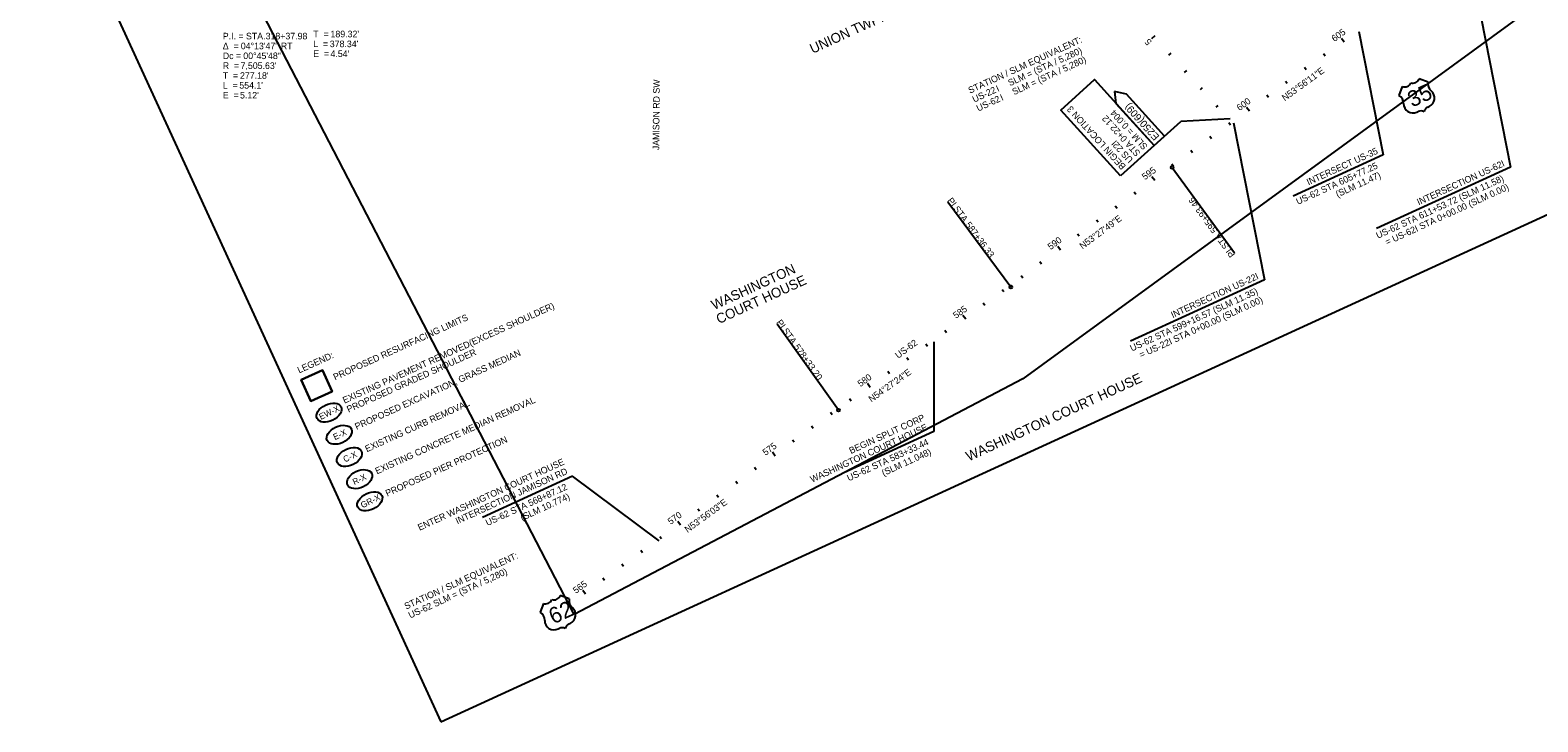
# Model space of a CAD drawing. Extents: x 127199 to 143299, y 479188 to 491521.
# Drawn here: x 127199 to 133628, y 479188 to 482138 of the extents above; entities that cross this region are included whole.
import ezdxf

# ---------------------------------------------------------------- set-up
doc = ezdxf.new("R2010")
doc.units = 0
for name, color, linetype in [('PM_P_CL_Double_Solid', 7, 'Continuous'), ('PM_X_CL_Double_Solid', 7, 'Continuous'), ('PM_X_CL_Pass_Proh_Lt', 7, 'Continuous'), ('PM_X_Crosswalk', 7, 'Continuous'), ('PM_X_Lane_Line', 7, 'Continuous'), ('PM_X_Stop_Line', 7, 'Continuous'), ('PV_X_Parking_Lot', 7, 'Continuous'), ('PV_X_Walk', 7, 'Continuous'), ('RD_X_RR_2', 7, 'Continuous'), ('SH_Data', 7, 'Continuous')]:
    doc.layers.add(name, color=color, linetype=linetype)

msp = doc.modelspace()

# ---------------------------------------------------------------- linework, layer by layer
at = {"layer": 'PM_P_CL_Double_Solid'}
msp.add_lwpolyline([(128487.4, 480597.5), (128396.5, 480555.8), (128354.8, 480646.7), (128445.7, 480688.4)], close=True, dxfattribs=at)
at = {"layer": 'PM_X_CL_Double_Solid'}
for p, q in [((132069.3, 481552.7), (132334.2, 481188.9)), ((131380.6, 481042.4), (131112.7, 481404)), ((130645.7, 480517.4), (130384.1, 480883.6))]:
    msp.add_line(p, q, dxfattribs=at)
for centre in [(132069.3, 481552.7), (131380.6, 481042.4), (130645.7, 480517.4)]:
    msp.add_circle(centre, 6, dxfattribs=at)
at = {"layer": 'PM_X_CL_Pass_Proh_Lt'}
for centre, major_axis in [((128474, 480506.8), (51.4, 24.9)), ((128517.4, 480412.2), (51.7, 24.5)), ((128560.8, 480317.5), (51.4, 24.9)), ((128604.2, 480222.9), (-51.4, -24.9)), ((128647.6, 480128.3), (51.4, 24.9))]:
    msp.add_ellipse(centre, major_axis=major_axis, ratio=0.62608, dxfattribs=at)
at = {"layer": 'PM_X_Crosswalk'}
for p, q in [((133049.6, 481897.4), (133035.7, 481859.7)), ((133159.7, 481916.6), (133122, 481930.6)), ((133158.6, 481809.8), (133163.8, 481812.1)), ((133112.1, 481788.4), (133117.3, 481790.8)), ((129387.7, 479693.2), (129373.7, 479655.5)), ((129497.7, 479712.3), (129460, 479726.3)), ((129450.1, 479584.2), (129455.3, 479586.6)), ((129496.6, 479605.5), (129501.8, 479607.9))]:
    msp.add_line(p, q, dxfattribs=at)
for centre, radius, start, end in [((133059.3, 481924.1), 28.4, 250.2093, 339.06331), ((133095.4, 481940.7), 28.4, 250.2093, 339.06331), ((133198.8, 481909.4), 39.8, 169.63538, 230.08918), ((133147.6, 481848.5), 39.8, 293.99804, 49.80439), ((133015.5, 481825.4), 39.8, 359.18343, 59.63724), ((133095.1, 481824.4), 39.8, 179.46823, 295.27457), ((133170.5, 481783.9), 28.4, 114.63631, 167.76641), ((133129.1, 481765), 28.4, 61.5062, 114.63631), ((129397.3, 479719.9), 28.4, 250.2093, 339.06331), ((129433.5, 479736.5), 28.4, 250.2093, 339.06331), ((129536.8, 479705.2), 39.8, 169.63538, 230.08918), ((129353.6, 479621.1), 39.8, 359.18343, 59.63724), ((129433.1, 479620.2), 39.8, 179.46823, 295.27457), ((129485.6, 479644.3), 39.8, 293.99804, 49.80439), ((129467.2, 479560.8), 28.4, 61.5062, 114.63631), ((129508.5, 479579.7), 28.4, 114.63631, 167.76641)]:
    msp.add_arc(centre, radius, start, end, dxfattribs=at)
at = {"layer": 'PM_X_Lane_Line'}
for p, q in [((133330.5, 482471.2), (133511.4, 481554.3)), ((132864.5, 482131.8), (132968.2, 481606.2)), ((131873.3, 481865.4), (131822.7, 481877)), ((131822.7, 481877), (131829.1, 481825.5)), ((131829.1, 481825.5), (131991.5, 481645.7)), ((132035.7, 481685.6), (131873.3, 481865.4)), ((131991.5, 481645.7), (132105.9, 481749)), ((132315.6, 481759.3), (132105.9, 481749)), ((132330.5, 481742.9), (132462.5, 481073.3)), ((131991.5, 481645.7), (132035.7, 481685.6)), ((132968.2, 481606.2), (132584.1, 481430.1)), ((133511.4, 481554.3), (132939.9, 481292.2)), ((132462.5, 481073.3), (131891.1, 480811.2)), ((131052.8, 480808.2), (131052.2, 480426.5)), ((131052.2, 480426.5), (130668.1, 480250.4)), ((129511.8, 480236.1), (129127.7, 480059.9)), ((129881, 479960.4), (129511.8, 480236.1))]:
    msp.add_line(p, q, dxfattribs=at)
msp.add_lwpolyline([(131848, 481516), (131593.9, 481797.2), (131737.4, 481926.9), (131991.5, 481645.7)], close=True, dxfattribs=at)
at = {"layer": 'PV_X_Walk'}
for p, q in [((131995.3, 482113.9), (131980.4, 482100.5)), ((132802.1, 482086.4), (132790.3, 482102.5)), ((132062.3, 482039.7), (132053.4, 482031.7)), ((132721.2, 482027.5), (132714.2, 482037.2)), ((132129.3, 481965.5), (132120.4, 481957.5)), ((132640.4, 481968.6), (132633.3, 481978.3)), ((132196.4, 481891.3), (132187.5, 481883.3)), ((132559.6, 481909.8), (132552.5, 481919.5)), ((132263.4, 481817.1), (132254.5, 481809.1)), ((132397.9, 481792), (132386.1, 481808.2)), ((132478.7, 481850.9), (132471.7, 481860.6)), ((132317.1, 481733.2), (132310, 481742.9)), ((132236.2, 481674.3), (132229.2, 481684)), ((132155.4, 481615.4), (132148.3, 481625.1)), ((132074.5, 481556.6), (132067.5, 481566.3)), ((131994.2, 481497.1), (131982.3, 481513.1)), ((131913.8, 481437.5), (131906.7, 481447.2)), ((131833.5, 481378), (131826.3, 481387.6)), ((131753.1, 481318.5), (131746, 481328.1)), ((131672.8, 481258.9), (131665.6, 481268.6)), ((131592.4, 481199.4), (131580.5, 481215.5)), ((131512.1, 481139.9), (131504.9, 481149.5)), ((131351, 481021.3), (131344, 481031.1)), ((131431.7, 481080.3), (131424.6, 481090)), ((131269.6, 480963.2), (131262.7, 480972.9)), ((131188.3, 480905), (131176.7, 480921.3)), ((131106.9, 480846.9), (131099.9, 480856.7)), ((131025.5, 480788.8), (131018.6, 480798.5)), ((130944.2, 480730.6), (130937.2, 480740.4)), ((130862.8, 480672.5), (130855.8, 480682.3)), ((130781.4, 480614.4), (130769.8, 480630.7)), ((130700.1, 480556.3), (130693.1, 480566)), ((130618.9, 480497.9), (130611.8, 480507.6)), ((130457.2, 480380.1), (130450.1, 480389.8)), ((130538, 480439), (130531, 480448.7)), ((130376.4, 480321.3), (130364.6, 480337.4)), ((130295.5, 480262.4), (130288.5, 480272.1)), ((130214.7, 480203.5), (130207.6, 480213.2)), ((130133.9, 480144.6), (130126.8, 480154.3)), ((130053, 480085.8), (130046, 480095.5)), ((129972.2, 480026.9), (129960.4, 480043.1)), ((129891.4, 479968), (129884.3, 479977.7)), ((129810.5, 479909.2), (129803.5, 479918.9)), ((129729.7, 479850.3), (129722.6, 479860)), ((129568, 479732.5), (129556.3, 479748.7)), ((129648.9, 479791.4), (129641.8, 479801.1))]:
    msp.add_line(p, q, dxfattribs=at)
at = {"layer": 'RD_X_RR_2'}
for p, q in [((137214.6, 484869.1), (131432.3, 480651.5)), ((129519.3, 479645.5), (127687.9, 483180.9)), ((127199.5, 483005.6), (128950.3, 479187.9)), ((128950.3, 479187.9), (134131.4, 481564)), ((131432.3, 480651.5), (129519.3, 479645.5))]:
    msp.add_line(p, q, dxfattribs=at)
at = {"layer": 'SH_Data'}
msp.add_lwpolyline([(128445.7, 480688.4), (128354.8, 480646.7), (128396.5, 480555.8), (128487.4, 480597.5)], close=True, dxfattribs=at)

# ---------------------------------------------------------------- texts
at = {"layer": 'PM_X_CL_Double_Solid'}
for s, rotation, p in [('PI', 306.53645, (131108.1, 481410.8)), ('595+93.46', 126.0636, (132263.6, 481285.2)), (' STA. ', 306.53645, (131128.3, 481383.6)), ('587+36.33', 306.53645, (131184.6, 481307.6)), (' STA. ', 126.0636, (132319.2, 481208.8)), ('PI', 126.0636, (132339.2, 481181.4)), ('PI', 305.54343, (130379.3, 480891.1)), (' STA. ', 305.54343, (130399, 480863.5)), ('578+33.20', 305.54343, (130453.9, 480786.6))]:
    msp.add_text(s, height=28, rotation=rotation, dxfattribs=at).set_placement(p)
at = {"layer": 'PM_X_CL_Pass_Proh_Lt'}
for s, height, rotation, p in [('EXISTING PAVEMENT REMOVED(EXCESS SHOULDER)', 28, 24.39077, (128539.7, 480544.8)), ('PROPOSED RESURFACING LIMITS', 28, 24.39077, (128499.5, 480644)), ('PROPOSED GRADED SHOULDER', 28, 24.39077, (128557, 480506.5)), ('PROPOSED EXCAVATION, GRASS MEDIAN', 28, 24.39077, (128591.4, 480433)), ('LEGEND:', 28, 24.39077, (128346.6, 480673.7)), ('EW-X', 26.25, 25.85115, (128439.1, 480475.3)), ('EXISTING CURB REMOVAL', 28, 24.39077, (128635.1, 480337.6)), ('EXISTING CONCRETE MEDIAN REMOVAL', 28, 24.39077, (128678.2, 480243.1)), ('E-X', 26.25, 25.35958, (128498.9, 480388.9)), ('PROPOSED PIER PROTECTION', 28, 24.39077, (128722.1, 480148.3)), ('C-X', 26.25, 25.85115, (128541.7, 480293.7)), ('R-X', 26.25, 25.85115, (128581.8, 480197.5)), ('GR-X', 26.25, 25.85115, (128616.5, 480098.7))]:
    msp.add_text(s, height=height, rotation=rotation, dxfattribs=at).set_placement(p)
at = {"layer": 'PM_X_Crosswalk'}
for s, p in [('35', (133092, 481807.4)), ('62', (129430.2, 479603.2))]:
    msp.add_text(s, height=68.22, rotation=24.63631, dxfattribs=at).set_placement(p)
at = {"layer": 'PM_X_Lane_Line'}
for s, height, rotation, p in [('UNION TWP.', 42, 24.63631, (130535.7, 482036.8)), ('STATION / SLM EQUIVALENT:', 28, 24.63631, (131206.9, 481866.9)), ('SLM = (STA / 5,280)', 28, 24.63631, (131376.8, 481898.6)), ('SLM = (STA / 5,280)', 28, 24.63631, (131394.3, 481860.4)), ('JAMISON RD SW', 28, 89.49852, (129881.5, 481626)), ('US-22', 28, 24.63631, (131224.4, 481828.7)), ('I ', 28, 24.63631, (131325.2, 481874.9)), ('US-62', 28, 24.63631, (131241.9, 481790.5)), ('I ', 28, 24.63631, (131342.7, 481836.7)), ('BEGIN LOCATION 3', 28, 132.22497, (131873.1, 481558.5)), ('E250(609)', 31.2, 132.22497, (132016.3, 481685.1)), ('STA 0+22.12', 28, 132.22497, (131935.3, 481615)), ('SLM = 0.004', 28, 132.22497, (131966.4, 481643.2)), ('I', 28, 132.22497, (131835, 481663)), ('US 22', 28, 132.22497, (131904.2, 481586.8)), ('INTERSECT US-35', 28, 24.63631, (132649.9, 481475.7)), ('US-62 STA 605+77.25', 28, 24.63631, (132604.8, 481392.6)), ('INTERSECTION US-62I ', 28, 24.63631, (133120.1, 481390.3)), ('(SLM 11.47)', 28, 24.63631, (132774, 481424)), ('US-62 STA 611+53.72 (SLM 11.58)', 28, 24.63631, (132945.8, 481248)), ('= US-62I STA 0+00.00 (SLM 0.00)', 28, 24.63631, (132985.1, 481219.8)), ('WASHINGTON ', 42, 24.63631, (130115.7, 480943.8)), ('INTERSECTION US-22I ', 28, 24.63631, (132071.2, 480909.3)), ('COURT HOUSE', 42, 24.63631, (130136.4, 480884)), ('US-62 STA 599+16.57 (SLM 11.35)', 28, 24.63631, (131896.9, 480767)), ('= US-22I STA 0+00.00 (SLM 0.00)', 28, 24.63631, (131936.2, 480738.8)), ('US-62', 28, 36.29117, (130900.1, 480735.9)), ('WASHINGTON COURT HOUSE', 42, 24.63631, (131201.3, 480298.4)), ('WASHINGTON COURT HOUSE', 28, 24.63631, (130533.4, 480207.7)), ('BEGIN SPLIT CORP', 28, 24.63631, (130699.1, 480329.9)), ('US-62 STA 583+33.44', 28, 24.63631, (130690, 480213.5)), ('(SLM 11.048)', 28, 24.63631, (130838.3, 480235.3)), ('ENTER WASHINGTON COURT HOUSE', 28, 24.63631, (128860, 480002.5)), ('INTERSECTION JAMISON RD', 28, 24.63631, (129021.1, 480030.2)), ('US-62 STA 568+87.12', 28, 24.63631, (129148.9, 480022.7)), ('(SLM 10.774)', 28, 24.63631, (129297.3, 480044.6)), ('STATION / SLM EQUIVALENT:', 28, 24.63631, (128802.5, 479666.4)), ('US-62 SLM = (STA / 5,280)', 28, 24.63631, (128820, 479628.2))]:
    msp.add_text(s, height=height, rotation=rotation, dxfattribs=at).set_placement(p)
at = {"layer": 'PM_X_Stop_Line'}
for s, p in [('P.I. = STA. ', (128020.9, 482098.6)), ('318+37.98', (128203.5, 482098.6)), ('T  = ', (128406.7, 482107.5)), ("189.32'", (128480.1, 482107.5)), ('Δ  = ', (128020.9, 482056.6)), ('04°13\'47" RT', (128097.6, 482056.6)), ('L  = ', (128406.7, 482065.5)), ("378.34'", (128477.1, 482065.5)), ('Dc = ', (128020.9, 482014.6)), ('R  = ', (128020.9, 481972.6)), ("7,505.63'", (128096.7, 481972.6)), ('00°45\'48"', (128108.3, 482014.6)), ('E  = ', (128406.7, 482023.5)), ("4.54'", (128480.1, 482023.5)), ('T  = ', (128020.9, 481930.6)), ("277.18'", (128094.2, 481930.6)), ('L  = ', (128020.9, 481888.6)), ('E  = ', (128020.9, 481846.6)), ("554.1'", (128091.3, 481888.6)), ("5.12'", (128094.3, 481846.6))]:
    msp.add_text(s, height=28, dxfattribs=at).set_placement(p)
at = {"layer": 'PV_X_Parking_Lot'}
for s, rotation, p in [('N53°56\'11"E', 36.0636, (132548.8, 481834.3)), ('N53°27\'49"E', 36.53645, (131686.3, 481202.6)), ('N54°27\'24"E', 35.54343, (130786.3, 480549.7)), ('N53°56\'03"E', 36.06583, (130002.5, 479993.2))]:
    msp.add_text(s, height=28, rotation=rotation, dxfattribs=at).set_placement(p)
at = {"layer": 'PV_X_Walk'}
for s, rotation, p in [('605', 36.0636, (132760.6, 482087.1)), ('5', 132.09501, (131983.9, 482089.2)), ('600', 36.0636, (132356.1, 481792.5)), ('595', 36.53645, (131952.7, 481497.5)), ('590', 36.53645, (131550.7, 481199.6)), ('585', 35.54343, (131146.9, 480906.2)), ('580', 35.54343, (130739.7, 480615.3)), ('575', 36.06583, (130334.9, 480322)), ('570', 36.06583, (129930.4, 480027.4)), ('565', 36.06583, (129526.6, 479733.3))]:
    msp.add_text(s, height=28, rotation=rotation, dxfattribs=at).set_placement(p)

doc.saveas('drawing.dxf')
